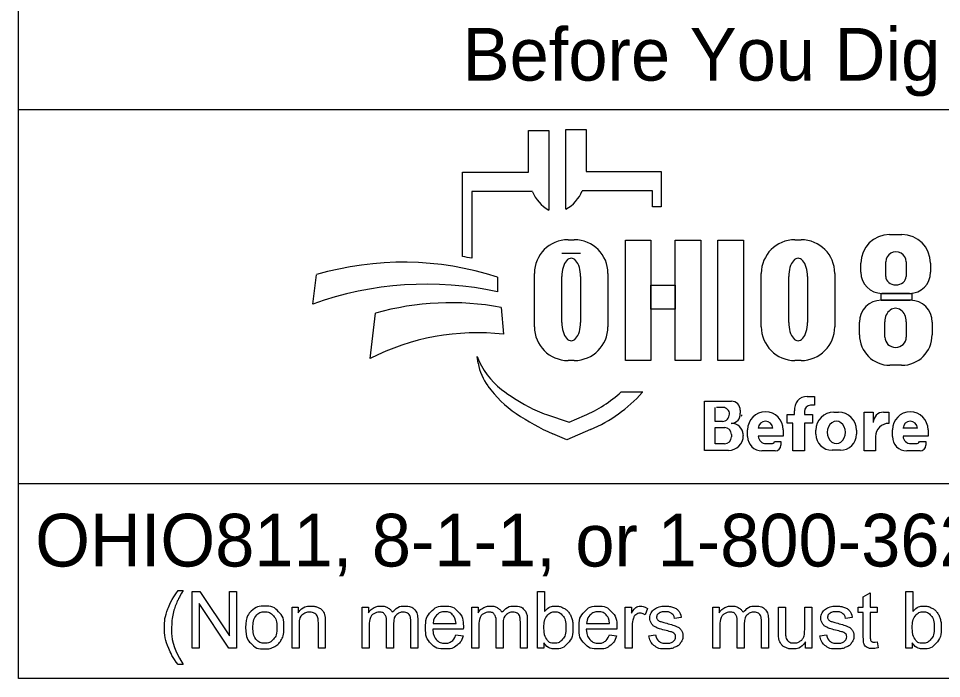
# Model space of a CAD drawing. Extents: x 0 to 51, y -1.2 to 22.
# Drawn here: x 2.978 to 5.431, y 2.143 to 3.897 of the extents above; entities that cross this region are included whole.
import ezdxf

# ---------------------------------------------------------------- set-up
doc = ezdxf.new("R2010")
doc.units = 0
doc.layers.add('SH_Text', color=7, linetype='Continuous')

msp = doc.modelspace()

# ---------------------------------------------------------------- linework, layer by layer
at = {"layer": 'SH_Text'}
for p, q in [((2.9775, 2.1428), (2.9775, 4.4803)), ((2.9775, 3.6553), (7.2275, 3.6553)), ((4.3335, 3.4883), (4.3335, 3.5998)), ((4.3335, 3.5998), (4.3872, 3.5998)), ((4.3872, 3.5998), (4.3872, 3.3877)), ((4.4329, 3.39), (4.4329, 3.6021)), ((4.4329, 3.6021), (4.4865, 3.6021)), ((4.4865, 3.6021), (4.4865, 3.4906)), ((4.1576, 3.2644), (4.1576, 3.4883)), ((4.1576, 3.4883), (4.3335, 3.4883)), ((4.4865, 3.4906), (4.6857, 3.4906)), ((4.6857, 3.4906), (4.6857, 3.3968)), ((4.1828, 3.4369), (4.1828, 3.26)), ((4.3439, 3.4369), (4.1828, 3.4369)), ((4.6625, 3.4392), (4.4761, 3.4392)), ((4.6625, 3.3968), (4.6625, 3.4392)), ((4.6857, 3.3968), (4.6625, 3.3968)), ((5.2931, 3.3231), (5.3258, 3.3231)), ((4.4385, 3.3091), (4.4551, 3.3091)), ((5.0416, 3.3091), (5.0581, 3.3091)), ((4.4718, 3.2721), (4.422, 3.2721)), ((5.2168, 3.2225), (5.2168, 3.2468)), ((5.283, 3.2111), (5.283, 3.2504)), ((5.3371, 3.2504), (5.3371, 3.2111)), ((5.4022, 3.2468), (5.4022, 3.2225)), ((3.7602, 3.1381), (3.7696, 3.2162)), ((4.3491, 3.0776), (4.3491, 3.2196)), ((4.5445, 3.2196), (4.5445, 3.0776)), ((4.9521, 3.0776), (4.9521, 3.2196)), ((5.1476, 3.2196), (5.1476, 3.0776)), ((4.2509, 3.2097), (4.2509, 3.1709)), ((4.422, 3.089), (4.422, 3.2114)), ((4.4718, 3.2114), (4.4718, 3.089)), ((5.025, 3.089), (5.025, 3.2114)), ((5.0748, 3.2114), (5.0748, 3.089)), ((5.3462, 3.1665), (5.2728, 3.1665)), ((5.271, 3.1482), (5.3483, 3.1482)), ((4.2608, 3.1291), (4.2671, 3.0582)), ((3.912, 2.9936), (3.9267, 3.1137)), ((5.2131, 3.0563), (5.2131, 3.0903)), ((5.2806, 3.0503), (5.2806, 3.0912)), ((5.3374, 3.0912), (5.3374, 3.0503)), ((5.4062, 3.0903), (5.4062, 3.0563)), ((4.1997, 2.9807), (4.1967, 2.9986)), ((4.4551, 2.9882), (4.4385, 2.9882)), ((5.0581, 2.9882), (5.0416, 2.9882)), ((5.3252, 2.9753), (5.2941, 2.9753)), ((4.58, 2.9048), (4.6375, 2.9048)), ((4.8013, 2.749), (4.8013, 2.8798)), ((4.8013, 2.8798), (4.8725, 2.8798)), ((5.0739, 2.8926), (5.0934, 2.8926)), ((5.0934, 2.8926), (5.0934, 2.8696)), ((4.8293, 2.8263), (4.8293, 2.8632)), ((4.8545, 2.8632), (4.8332, 2.8632)), ((4.8963, 2.856), (4.8963, 2.8481)), ((5.0406, 2.8442), (5.0406, 2.8546)), ((5.0667, 2.8526), (5.0667, 2.8442)), ((5.0934, 2.8691), (5.0832, 2.8691)), ((5.1451, 2.8508), (5.1573, 2.8508)), ((5.2254, 2.7478), (5.2254, 2.8505)), ((5.2254, 2.8505), (5.2499, 2.8505)), ((5.2499, 2.8505), (5.2499, 2.8237)), ((5.2772, 2.8505), (5.291, 2.8505)), ((5.291, 2.8505), (5.291, 2.8209)), ((4.3816, 2.8444), (4.441, 2.8239)), ((4.441, 2.8239), (4.4821, 2.8417)), ((4.8487, 2.8263), (4.8293, 2.8263)), ((5.0213, 2.8212), (5.0213, 2.8442)), ((5.0213, 2.8442), (5.0406, 2.8442)), ((5.0667, 2.8442), (5.0883, 2.8442)), ((5.0883, 2.8442), (5.0883, 2.8212)), ((4.4983, 2.8044), (4.435, 2.7769)), ((4.8293, 2.7669), (4.8293, 2.8097)), ((4.8293, 2.8097), (4.8548, 2.8097)), ((4.9159, 2.7858), (4.9159, 2.8042)), ((4.9824, 2.8082), (4.9439, 2.8082)), ((5.0104, 2.8042), (5.0104, 2.7866)), ((5.0362, 2.8212), (5.0213, 2.8212)), ((5.0362, 2.7478), (5.0362, 2.8212)), ((5.0883, 2.8212), (5.0667, 2.8212)), ((5.0667, 2.8212), (5.0667, 2.7478)), ((5.0973, 2.7922), (5.0973, 2.8029)), ((5.2051, 2.8029), (5.2051, 2.7922)), ((5.3008, 2.7858), (5.3008, 2.8042)), ((5.3674, 2.8082), (5.3288, 2.8082)), ((5.3953, 2.8042), (5.3953, 2.7866)), ((4.435, 2.7769), (4.3976, 2.7934)), ((4.8729, 2.7916), (4.8729, 2.7853)), ((4.9043, 2.7887), (4.9043, 2.7884)), ((5.0104, 2.7866), (4.944, 2.7866)), ((4.9876, 2.7729), (5.0045, 2.7729)), ((5.0045, 2.7729), (5.0045, 2.7631)), ((5.2559, 2.786), (5.2559, 2.7478)), ((5.3953, 2.7866), (5.3289, 2.7866)), ((5.3725, 2.7729), (5.3894, 2.7729)), ((5.3894, 2.7729), (5.3894, 2.7631)), ((4.865, 2.749), (4.8013, 2.749)), ((4.8546, 2.7669), (4.8293, 2.7669)), ((4.9649, 2.7673), (4.979, 2.7673)), ((5.1623, 2.7494), (5.1401, 2.7494)), ((5.3498, 2.7673), (5.3639, 2.7673)), ((4.9892, 2.7478), (4.9538, 2.7478)), ((5.0667, 2.7478), (5.0362, 2.7478)), ((5.2559, 2.7478), (5.2254, 2.7478)), ((5.3742, 2.7478), (5.3388, 2.7478)), ((7.2275, 2.6607), (2.9775, 2.6607)), ((7.2275, 2.1428), (2.9775, 2.1428))]:
    msp.add_line(p, q, dxfattribs=at)
for points in [[(4.591, 3.3081), (4.6589, 3.3081), (4.6589, 2.9881), (4.591, 2.9881)], [(4.7231, 3.3081), (4.7911, 3.3081), (4.7911, 2.9881), (4.7231, 2.9881)], [(4.8364, 3.3081), (4.9052, 3.3081), (4.9052, 2.9881), (4.8364, 2.9881)], [(4.6589, 3.1882), (4.7231, 3.1882), (4.7231, 3.1242), (4.6589, 3.1242)], [(5.2706, 3.1665), (5.3523, 3.1665), (5.3523, 3.1481), (5.2706, 3.1481)]]:
    msp.add_lwpolyline(points, close=True, dxfattribs=at)
for points in [[(3.4021, 2.3766), (3.4153, 2.3766)], [(3.4389, 2.2239), (3.4389, 2.3741), (3.4592, 2.3741), (3.5382, 2.2561), (3.5382, 2.3741), (3.5572, 2.3741), (3.5572, 2.2239), (3.5369, 2.2239), (3.4579, 2.3419), (3.4579, 2.2239), (3.4389, 2.2239)], [(4.3743, 2.2239), (4.3573, 2.2239), (4.3573, 2.3741), (4.3757, 2.3741), (4.3757, 2.3206)], [(5.2233, 2.2558), (5.2233, 2.3185), (5.2097, 2.3185), (5.2097, 2.3328), (5.2233, 2.3328), (5.2233, 2.3597), (5.2417, 2.3708), (5.2417, 2.3328), (5.2601, 2.3328), (5.2601, 2.3185), (5.2417, 2.3185), (5.2417, 2.2547)], [(5.3534, 2.2239), (5.3363, 2.2239), (5.3363, 2.3741), (5.3548, 2.3741), (5.3548, 2.3206)], [(3.7048, 2.2239), (3.7048, 2.3328), (3.7214, 2.3328), (3.7214, 2.3173)], [(3.8912, 2.2239), (3.8912, 2.3328), (3.9077, 2.3328), (3.9077, 2.3174)], [(4.1826, 2.2239), (4.1826, 2.3328), (4.1991, 2.3328), (4.1991, 2.3174)], [(4.5904, 2.2239), (4.5904, 2.3328), (4.607, 2.3328), (4.607, 2.3163)], [(4.8236, 2.2239), (4.8236, 2.3328), (4.8401, 2.3328), (4.8401, 2.3174)], [(4.9979, 2.2654), (4.9979, 2.3328), (5.0164, 2.3328), (5.0164, 2.2724)], [(5.0676, 2.2745), (5.0676, 2.3328), (5.0861, 2.3328), (5.0861, 2.2239), (5.0696, 2.2239)], [(4.6495, 2.3293), (4.643, 2.3122)], [(3.7233, 2.2833), (3.7233, 2.2239), (3.7048, 2.2239)], [(3.7932, 2.2908), (3.7932, 2.2239), (3.7748, 2.2239), (3.7748, 2.2901)], [(3.9743, 2.2871), (3.9743, 2.2239), (3.9559, 2.2239), (3.9559, 2.2946)], [(4.0388, 2.2986), (4.0388, 2.2239), (4.0203, 2.2239), (4.0203, 2.2924)], [(4.0799, 2.2887), (4.1406, 2.2887)], [(4.2657, 2.2871), (4.2657, 2.2239), (4.2473, 2.2239), (4.2473, 2.2946)], [(4.3301, 2.2986), (4.3301, 2.2239), (4.3117, 2.2239), (4.3117, 2.2924)], [(4.4879, 2.2887), (4.5486, 2.2887)], [(4.7394, 2.3046), (4.7213, 2.3022)], [(4.9067, 2.2871), (4.9067, 2.2239), (4.8883, 2.2239), (4.8883, 2.2946)], [(4.9711, 2.2986), (4.9711, 2.2239), (4.9527, 2.2239), (4.9527, 2.2924)], [(5.194, 2.3046), (5.1759, 2.3022)], [(3.9097, 2.2803), (3.9097, 2.2239), (3.8912, 2.2239)], [(4.16, 2.2736), (4.0788, 2.2736)], [(4.1404, 2.2591), (4.1595, 2.2567)], [(4.201, 2.2803), (4.201, 2.2239), (4.1826, 2.2239)], [(4.568, 2.2736), (4.4868, 2.2736)], [(4.5484, 2.2591), (4.5675, 2.2567)], [(4.6088, 2.2809), (4.6088, 2.2239), (4.5904, 2.2239)], [(4.653, 2.2564), (4.6712, 2.2593)], [(4.842, 2.2803), (4.842, 2.2239), (4.8236, 2.2239)], [(5.1076, 2.2564), (5.1258, 2.2593)], [(4.3743, 2.2375), (4.3743, 2.2239)], [(5.0696, 2.2239), (5.0696, 2.24)], [(5.2601, 2.2404), (5.2628, 2.2241)], [(5.3534, 2.2375), (5.3534, 2.2239)], [(3.4153, 2.1798), (3.4021, 2.1798)]]:
    msp.add_lwpolyline(points, dxfattribs=at)
for centre, radius, start, end in [((4.4353, 3.4736), 0.0985, 201.9296, 240.7469), ((4.3847, 3.476), 0.0985, 299.2531, 338.0704), ((5.2931, 3.2468), 0.0763, 90, 180), ((5.3258, 3.2468), 0.0763, 0, 90), ((4.4385, 3.2196), 0.0895, 90, 180), ((4.4551, 3.2196), 0.0895, 0, 90), ((5.0416, 3.2196), 0.0895, 90, 180), ((5.0581, 3.2196), 0.0895, 0, 90), ((4.0295, 2.4554), 0.8191, 79.2074, 81.0007), ((3.9997, 2.4302), 0.8191, 72.1402, 106.3144), ((5.2728, 3.2225), 0.056, 180, 270), ((5.3462, 3.2225), 0.056, 270, 0), ((4.0628, 2.2991), 0.8919, 77.8238, 109.8274), ((4.1267, 2.4094), 0.7322, 79.44, 105.8467), ((5.271, 3.0903), 0.0579, 90, 180), ((5.3483, 3.0903), 0.0579, 0, 90), ((4.4385, 3.0776), 0.0895, 180, 270), ((4.4551, 3.0776), 0.0895, 270, 0), ((5.0416, 3.0776), 0.0895, 180, 270), ((5.0581, 3.0776), 0.0895, 270, 0), ((4.1987, 2.4262), 0.6357, 83.8248, 116.8021), ((5.2941, 3.0563), 0.081, 180, 270), ((5.3252, 3.0563), 0.081, 270, 0), ((4.3841, 3.0707), 0.2008, 201.0457, 232.5314), ((4.341, 3.0048), 0.1433, 189.6817, 216.0884), ((4.4747, 3.1022), 0.3088, 216.0884, 235.7167), ((4.5766, 3.3219), 0.5173, 232.5314, 241.794), ((4.3387, 3.1722), 0.3602, 293.4582, 312.0712), ((4.3387, 3.1722), 0.401, 293.4582, 317.8286), ((4.8725, 2.856), 0.0238, 0, 90), ((5.0739, 2.859), 0.0335, 90, 187.5187), ((4.6412, 3.3465), 0.6044, 235.7167, 246.2325), ((4.4914, 3.1631), 0.3371, 241.794, 250.9821), ((4.8505, 2.8463), 0.0169, 357.8325, 90), ((4.8721, 2.8453), 0.0243, 270, 6.6529), ((4.9631, 2.8042), 0.0473, 0, 180), ((5.0832, 2.8526), 0.0165, 90, 180), ((5.1451, 2.8029), 0.0478, 90, 180), ((5.1573, 2.8029), 0.0478, 0, 90), ((5.2768, 2.8237), 0.0269, 89.2449, 180), ((5.3481, 2.8042), 0.0473, 0, 180), ((4.8487, 2.845), 0.0187, 270, 2.0582), ((4.8827, 2.8438), 0.0175, 347.4023, 0), ((4.9632, 2.8072), 0.0193, 2.9632, 177.0368), ((5.3481, 2.8072), 0.0193, 2.9632, 177.0368), ((4.8548, 2.7916), 0.0181, 0, 90), ((4.8722, 2.7889), 0.0321, 4.0748, 90), ((5.2908, 2.786), 0.0349, 89.6033, 180), ((4.8546, 2.7853), 0.0184, 270, 0), ((4.865, 2.7884), 0.0393, 270, 0), ((4.8714, 2.7887), 0.033, 0, 11.7502), ((4.9538, 2.7858), 0.038, 180, 270), ((4.9649, 2.7883), 0.021, 184.827, 270), ((4.979, 2.7767), 0.00938, 270, 335.9979), ((5.1401, 2.7922), 0.0428, 180, 270), ((5.1623, 2.7922), 0.0428, 270, 0), ((5.3388, 2.7858), 0.038, 180, 270), ((5.3498, 2.7883), 0.021, 184.827, 270), ((5.3639, 2.7767), 0.00938, 270, 335.9979), ((4.9892, 2.7631), 0.0152, 270, 0), ((5.3742, 2.7631), 0.0152, 270, 0)]:
    msp.add_arc(centre, radius, start, end, dxfattribs=at)
for centre, major_axis, ratio, start_param, end_param in [((5.31, 3.2504), (0.0271, 0), 0.969373, 0, 3.141593), ((4.4469, 3.2114), (0, 0.0484), 0.514403, 4.712389, 7.853982), ((5.0499, 3.2114), (0, 0.0484), 0.514403, 4.712389, 7.853982), ((5.31, 3.2111), (0.0271, 0), 0.818453, 3.141593, 6.283185), ((5.309, 3.0912), (0, 0.0358), 0.794529, 4.712389, 7.853982), ((4.4469, 3.089), (0, 0.0484), 0.514403, 1.570796, 4.712389), ((5.0499, 3.089), (0, 0.0484), 0.514403, 1.570796, 4.712389), ((5.309, 3.0503), (0.0284, 0), 0.959837, 3.141593, 6.283185), ((5.1517, 2.7976), (0, 0.029), 0.832186, 4.712389, 7.853982), ((5.1517, 2.7976), (0, 0.0302), 0.797287, 1.570796, 4.712389)]:
    msp.add_ellipse(centre, major_axis=major_axis, ratio=ratio, start_param=start_param, end_param=end_param, dxfattribs=at)
for points in [[(3.4021, 2.1798), (3.3869, 2.199), (3.3763, 2.2248), (3.3657, 2.2506), (3.3657, 2.2783), (3.3657, 2.3026), (3.3736, 2.325), (3.3829, 2.3509), (3.4021, 2.3766)], [(3.4153, 2.3766), (3.4029, 2.3553), (3.3989, 2.3462), (3.3927, 2.332), (3.3891, 2.3167), (3.3847, 2.2975), (3.3847, 2.2782), (3.3847, 2.2289), (3.4153, 2.1798)], [(3.5814, 2.2783), (3.5814, 2.3085), (3.5981, 2.3231), (3.6122, 2.3352), (3.6323, 2.3352), (3.6547, 2.3352), (3.669, 2.3205), (3.6832, 2.3058), (3.6832, 2.2799), (3.6832, 2.2589), (3.6769, 2.2469), (3.6706, 2.2348), (3.6586, 2.2282), (3.6466, 2.2215), (3.6323, 2.2215), (3.6095, 2.2215), (3.5954, 2.2362), (3.5814, 2.2508), (3.5814, 2.2783)], [(3.7214, 2.3173), (3.7334, 2.3352), (3.756, 2.3352), (3.7659, 2.3352), (3.7741, 2.3316), (3.7823, 2.3281), (3.7864, 2.3224), (3.7905, 2.3166), (3.7922, 2.3087), (3.7932, 2.3036), (3.7932, 2.2908)], [(3.9077, 2.3174), (3.9128, 2.3254), (3.9214, 2.3303), (3.9299, 2.3352), (3.9407, 2.3352), (3.9528, 2.3352), (3.9606, 2.3301), (3.9683, 2.3251), (3.9715, 2.3161), (3.9844, 2.3352), (4.0051, 2.3352), (4.0213, 2.3352), (4.03, 2.3262), (4.0388, 2.3172), (4.0388, 2.2986)], [(4.1595, 2.2567), (4.155, 2.24), (4.1428, 2.2307), (4.1306, 2.2215), (4.1117, 2.2215), (4.0878, 2.2215), (4.0738, 2.2362), (4.0598, 2.2509), (4.0598, 2.2774), (4.0598, 2.3049), (4.074, 2.32), (4.0881, 2.3352), (4.1106, 2.3352), (4.1324, 2.3352), (4.1463, 2.3203), (4.1601, 2.3055), (4.1601, 2.2785), (4.1601, 2.2769), (4.16, 2.2736)], [(4.1991, 2.3174), (4.2042, 2.3254), (4.2127, 2.3303), (4.2212, 2.3352), (4.2321, 2.3352), (4.2442, 2.3352), (4.2519, 2.3301), (4.2597, 2.3251), (4.2628, 2.3161), (4.2758, 2.3352), (4.2965, 2.3352), (4.3127, 2.3352), (4.3214, 2.3262), (4.3301, 2.3172), (4.3301, 2.2986)], [(4.3757, 2.3206), (4.3874, 2.3352), (4.4055, 2.3352), (4.4155, 2.3352), (4.4245, 2.3311), (4.4335, 2.3271), (4.4392, 2.3198), (4.445, 2.3124), (4.4483, 2.3021), (4.4516, 2.2918), (4.4516, 2.28), (4.4516, 2.252), (4.4378, 2.2368), (4.4239, 2.2215), (4.4046, 2.2215), (4.3853, 2.2215), (4.3743, 2.2375)], [(4.5675, 2.2567), (4.563, 2.24), (4.5508, 2.2307), (4.5386, 2.2215), (4.5196, 2.2215), (4.4958, 2.2215), (4.4818, 2.2362), (4.4678, 2.2509), (4.4678, 2.2774), (4.4678, 2.3049), (4.482, 2.32), (4.4961, 2.3352), (4.5186, 2.3352), (4.5404, 2.3352), (4.5543, 2.3203), (4.5681, 2.3055), (4.5681, 2.2785), (4.5681, 2.2769), (4.568, 2.2736)], [(4.607, 2.3163), (4.6133, 2.3278), (4.6187, 2.3315), (4.6241, 2.3352), (4.6305, 2.3352), (4.6398, 2.3352), (4.6495, 2.3293)], [(4.6712, 2.2593), (4.6727, 2.2483), (4.6798, 2.2425), (4.6868, 2.2366), (4.6995, 2.2366), (4.7122, 2.2366), (4.7184, 2.2418), (4.7245, 2.247), (4.7245, 2.254), (4.7245, 2.2602), (4.7191, 2.2638), (4.7153, 2.2663), (4.7002, 2.2701), (4.6799, 2.2752), (4.672, 2.2789), (4.6642, 2.2827), (4.6601, 2.2893), (4.6561, 2.2959), (4.6561, 2.3038), (4.6561, 2.3111), (4.6594, 2.3173), (4.6628, 2.3235), (4.6685, 2.3276), (4.6728, 2.3308), (4.6803, 2.333), (4.6877, 2.3352), (4.6962, 2.3352), (4.709, 2.3352), (4.7187, 2.3315), (4.7284, 2.3278), (4.733, 2.3215), (4.7377, 2.3152), (4.7394, 2.3046)], [(4.8401, 2.3174), (4.8452, 2.3254), (4.8537, 2.3303), (4.8622, 2.3352), (4.8731, 2.3352), (4.8852, 2.3352), (4.8929, 2.3301), (4.9007, 2.3251), (4.9038, 2.3161), (4.9168, 2.3352), (4.9375, 2.3352), (4.9537, 2.3352), (4.9624, 2.3262), (4.9711, 2.3172), (4.9711, 2.2986)], [(5.1258, 2.2593), (5.1273, 2.2483), (5.1343, 2.2425), (5.1414, 2.2366), (5.154, 2.2366), (5.1668, 2.2366), (5.1729, 2.2418), (5.1791, 2.247), (5.1791, 2.254), (5.1791, 2.2602), (5.1736, 2.2638), (5.1698, 2.2663), (5.1548, 2.2701), (5.1345, 2.2752), (5.1266, 2.2789), (5.1188, 2.2827), (5.1147, 2.2893), (5.1107, 2.2959), (5.1107, 2.3038), (5.1107, 2.3111), (5.114, 2.3173), (5.1173, 2.3235), (5.1231, 2.3276), (5.1274, 2.3308), (5.1348, 2.333), (5.1423, 2.3352), (5.1508, 2.3352), (5.1636, 2.3352), (5.1733, 2.3315), (5.183, 2.3278), (5.1876, 2.3215), (5.1922, 2.3152), (5.194, 2.3046)], [(5.3548, 2.3206), (5.3664, 2.3352), (5.3846, 2.3352), (5.3946, 2.3352), (5.4036, 2.3311), (5.4125, 2.3271), (5.4183, 2.3198), (5.4241, 2.3124), (5.4274, 2.3021), (5.4306, 2.2918), (5.4306, 2.28), (5.4306, 2.252), (5.4168, 2.2368), (5.403, 2.2215), (5.3836, 2.2215), (5.3644, 2.2215), (5.3534, 2.2375)], [(3.6003, 2.2783), (3.6003, 2.2574), (3.6094, 2.247), (3.6185, 2.2366), (3.6323, 2.2366), (3.646, 2.2366), (3.6551, 2.2471), (3.6642, 2.2575), (3.6642, 2.279), (3.6642, 2.2991), (3.6551, 2.3095), (3.6459, 2.3199), (3.6323, 2.3199), (3.6185, 2.3199), (3.6094, 2.3096), (3.6003, 2.2992), (3.6003, 2.2783)], [(3.7748, 2.2901), (3.7748, 2.3013), (3.7726, 2.3069), (3.7705, 2.3125), (3.765, 2.3158), (3.7595, 2.3191), (3.7521, 2.3191), (3.7404, 2.3191), (3.7318, 2.3117), (3.7233, 2.3042), (3.7233, 2.2833)], [(3.9559, 2.2946), (3.9559, 2.3069), (3.9514, 2.313), (3.9469, 2.3191), (3.9366, 2.3191), (3.9288, 2.3191), (3.9222, 2.315), (3.9156, 2.311), (3.9126, 2.3031), (3.9097, 2.2952), (3.9097, 2.2803)], [(4.0203, 2.2924), (4.0203, 2.3035), (4.0185, 2.3083), (4.0168, 2.3132), (4.012, 2.3162), (4.0073, 2.3191), (4.001, 2.3191), (3.9895, 2.3191), (3.9819, 2.3115), (3.9743, 2.3039), (3.9743, 2.2871)], [(4.1406, 2.2887), (4.1394, 2.3025), (4.1337, 2.3094), (4.1249, 2.3201), (4.1108, 2.3201), (4.0981, 2.3201), (4.0894, 2.3115), (4.0808, 2.303), (4.0799, 2.2887)], [(4.2473, 2.2946), (4.2473, 2.3069), (4.2428, 2.313), (4.2383, 2.3191), (4.228, 2.3191), (4.2202, 2.3191), (4.2136, 2.315), (4.207, 2.311), (4.204, 2.3031), (4.201, 2.2952), (4.201, 2.2803)], [(4.3117, 2.2924), (4.3117, 2.3035), (4.3099, 2.3083), (4.3081, 2.3132), (4.3034, 2.3162), (4.2987, 2.3191), (4.2923, 2.3191), (4.2809, 2.3191), (4.2733, 2.3115), (4.2657, 2.3039), (4.2657, 2.2871)], [(4.3741, 2.2792), (4.3741, 2.2596), (4.3794, 2.2509), (4.3881, 2.2366), (4.4029, 2.2366), (4.415, 2.2366), (4.4238, 2.2471), (4.4326, 2.2576), (4.4326, 2.2784), (4.4326, 2.2998), (4.4241, 2.3099), (4.4157, 2.3201), (4.4038, 2.3201), (4.3917, 2.3201), (4.3829, 2.3096), (4.3741, 2.299), (4.3741, 2.2792)], [(4.5486, 2.2887), (4.5474, 2.3025), (4.5417, 2.3094), (4.5328, 2.3201), (4.5188, 2.3201), (4.5061, 2.3201), (4.4974, 2.3115), (4.4888, 2.303), (4.4879, 2.2887)], [(4.643, 2.3122), (4.6363, 2.3162), (4.6295, 2.3162), (4.6235, 2.3162), (4.6187, 2.3125), (4.6139, 2.3089), (4.6119, 2.3024), (4.6088, 2.2926), (4.6088, 2.2809)], [(4.7213, 2.3022), (4.7201, 2.3106), (4.7142, 2.3153), (4.7083, 2.3201), (4.6975, 2.3201), (4.6848, 2.3201), (4.6794, 2.3159), (4.6739, 2.3116), (4.6739, 2.306), (4.6739, 2.3024), (4.6762, 2.2995), (4.6785, 2.2966), (4.6833, 2.2946), (4.686, 2.2936), (4.6996, 2.2899), (4.7192, 2.2847), (4.7269, 2.2813), (4.7347, 2.278), (4.7391, 2.2717), (4.7435, 2.2653), (4.7435, 2.2559), (4.7435, 2.2467), (4.7381, 2.2386), (4.7327, 2.2304), (4.7226, 2.226), (4.7124, 2.2215), (4.6996, 2.2215), (4.6784, 2.2215), (4.6672, 2.2303), (4.6561, 2.2391), (4.653, 2.2564)], [(4.8883, 2.2946), (4.8883, 2.3069), (4.8838, 2.313), (4.8793, 2.3191), (4.869, 2.3191), (4.8612, 2.3191), (4.8546, 2.315), (4.848, 2.311), (4.845, 2.3031), (4.842, 2.2952), (4.842, 2.2803)], [(4.9527, 2.2924), (4.9527, 2.3035), (4.9509, 2.3083), (4.9491, 2.3132), (4.9444, 2.3162), (4.9397, 2.3191), (4.9333, 2.3191), (4.9219, 2.3191), (4.9143, 2.3115), (4.9067, 2.3039), (4.9067, 2.2871)], [(5.1759, 2.3022), (5.1747, 2.3106), (5.1688, 2.3153), (5.1629, 2.3201), (5.1521, 2.3201), (5.1394, 2.3201), (5.1339, 2.3159), (5.1285, 2.3116), (5.1285, 2.306), (5.1285, 2.3024), (5.1308, 2.2995), (5.133, 2.2966), (5.1378, 2.2946), (5.1406, 2.2936), (5.1542, 2.2899), (5.1737, 2.2847), (5.1815, 2.2813), (5.1893, 2.278), (5.1937, 2.2717), (5.1981, 2.2653), (5.1981, 2.2559), (5.1981, 2.2467), (5.1927, 2.2386), (5.1873, 2.2304), (5.1772, 2.226), (5.167, 2.2215), (5.1542, 2.2215), (5.1329, 2.2215), (5.1218, 2.2303), (5.1107, 2.2391), (5.1076, 2.2564)], [(5.3532, 2.2792), (5.3532, 2.2596), (5.3585, 2.2509), (5.3672, 2.2366), (5.382, 2.2366), (5.3941, 2.2366), (5.4029, 2.2471), (5.4116, 2.2576), (5.4116, 2.2784), (5.4116, 2.2998), (5.4032, 2.3099), (5.3948, 2.3201), (5.3828, 2.3201), (5.3708, 2.3201), (5.362, 2.3096), (5.3532, 2.299), (5.3532, 2.2792)], [(4.0788, 2.2736), (4.0799, 2.2557), (4.089, 2.2462), (4.0981, 2.2366), (4.1117, 2.2366), (4.1219, 2.2366), (4.1291, 2.242), (4.1362, 2.2473), (4.1404, 2.2591)], [(4.4868, 2.2736), (4.4879, 2.2557), (4.497, 2.2462), (4.5061, 2.2366), (4.5197, 2.2366), (4.5299, 2.2366), (4.537, 2.242), (4.5442, 2.2473), (4.5484, 2.2591)], [(5.0696, 2.24), (5.0569, 2.2215), (5.0351, 2.2215), (5.0255, 2.2215), (5.0171, 2.2252), (5.0088, 2.2289), (5.0047, 2.2345), (5.0007, 2.2401), (4.9991, 2.2482), (4.9979, 2.2536), (4.9979, 2.2654)], [(5.0164, 2.2724), (5.0164, 2.258), (5.0175, 2.253), (5.0192, 2.2457), (5.0249, 2.2416), (5.0305, 2.2374), (5.0388, 2.2374), (5.0471, 2.2374), (5.0543, 2.2417), (5.0616, 2.2459), (5.0646, 2.2533), (5.0676, 2.2606), (5.0676, 2.2745)], [(5.2628, 2.2241), (5.255, 2.2224), (5.2488, 2.2224), (5.2388, 2.2224), (5.2333, 2.2256), (5.2278, 2.2288), (5.2255, 2.234), (5.2233, 2.2392), (5.2233, 2.2558)], [(5.2417, 2.2547), (5.2417, 2.2468), (5.2427, 2.2445), (5.2436, 2.2423), (5.2458, 2.2409), (5.248, 2.2396), (5.2521, 2.2396), (5.2551, 2.2396), (5.2601, 2.2404)]]:
    msp.add_open_spline(points, degree=3, dxfattribs=at)

# ---------------------------------------------------------------- texts
for s, p in [('Before You Dig', (4.1583, 3.7321)), ('OHIO811, 8-1-1, or 1-800-362-2764', (3.022, 2.4406))]:
    msp.add_text(s, height=0.14, dxfattribs=at).set_placement(p)

doc.saveas('drawing.dxf')
